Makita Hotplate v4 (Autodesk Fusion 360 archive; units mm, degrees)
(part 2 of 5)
extrude "Extrude34" add of existing geometry to an object second side blind 75
extrude "Extrude35" add of existing geometry blind 5
extrude "Extrude36" cut of existing geometry blind -12 second side blind 30
extrude "Extrude37" add of existing geometry to an object second side blind 0
extrude "Extrude38" cut of existing geometry blind 65
sketch "Sketch30" plane through (0, -5, 0) normal (0, -1, 0) x axis (1, 0, 0)
  line L1 (140.75, 37) -> (140.75, 20)
  line L2 (149.25, 37) -> (140.75, 37)
  line L3 (149.25, 20) -> (149.25, 37)
  line L4 (140.75, 20) -> (149.25, 20)
  line L5 (151.0284, 39) -> (160, 39)
  curve K1 (151.0284, 39) -> (148.2, 41.8284)
  line L6 (148.2, 46) -> (148.2, 41.8284)
  line L7 (142.2, 46) -> (148.2, 46)
  line L8 (142.2, 63) -> (142.2, 46)
  line L9 (148.2, 63) -> (142.2, 63)
  line L10 (148.2, 65.1716) -> (148.2, 63)
  curve K2 (148.2, 65.1716) -> (151.0284, 68)
  line L11 (160, 68) -> (151.0284, 68)
  line L12 (136.3688, 74.3543) -> (162.8374, 74.3543)
  line L13 (136.3688, 86.3543) -> (136.3688, 74.3543)
  line L14 (162.8374, 86.3543) -> (136.3688, 86.3543)
  line L15 (162.8374, 74.3543) -> (162.8374, 86.3543)
  line L16 (162.8374, 9.3543) -> (136.3688, 9.3543)
  line L17 (162.8374, 0) -> (162.8374, 9.3543)
  line L18 (188, 0) -> (162.8374, 0)
  line L19 (188, 120) -> (188, 0)
  line L20 (105.65, 120) -> (188, 120)
  line L21 (105.65, 114) -> (105.65, 120)
  line L22 (109.65, 114) -> (105.65, 114)
  line L23 (109.65, 96.75) -> (109.65, 114)
  line L24 (107, 96.75) -> (109.65, 96.75)
  line L25 (107, 23.25) -> (107, 96.75)
  line L26 (104.5, 23.25) -> (107, 23.25)
  line L27 (104.5, 15.3775) -> (104.5, 23.25)
  line L28 (108.4, 12) -> (104.5, 15.3775)
  line L29 (104.5, 8.6225) -> (108.4, 12)
  line L30 (104.5, 0) -> (104.5, 8.6225)
  line L31 (136.3688, 0) -> (104.5, 0)
  line L32 (136.3688, 9.3543) -> (136.3688, 0)
  line L33 (162.8374, 86.3543) -> (136.3688, 86.3543)
  line L34 (162.8374, 74.3543) -> (162.8374, 86.3543)
  line L35 (136.3688, 74.3543) -> (162.8374, 74.3543)
  line L36 (136.3688, 86.3543) -> (136.3688, 74.3543)
  line L37 (162.8374, 9.3543) -> (136.3688, 9.3543)
  line L38 (162.8374, 0) -> (162.8374, 9.3543)
  line L39 (136.3688, 0) -> (162.8374, 0)
  line L40 (136.3688, 9.3543) -> (136.3688, 0)
  line L41 (134.3688, 11.3543) -> (134.3688, -2)
  line L42 (164.8374, 11.3543) -> (134.3688, 11.3543)
  line L43 (164.8374, -2) -> (164.8374, 11.3543)
  line L44 (134.3688, -2) -> (164.8374, -2)
  line L45 (134.3688, 72.3543) -> (164.8374, 72.3543)
  line L46 (134.3688, 88.3543) -> (134.3688, 72.3543)
  line L47 (164.8374, 88.3543) -> (134.3688, 88.3543)
  line L48 (164.8374, 72.3543) -> (164.8374, 88.3543)
  line L49 (129.3688, 67.3543) -> (169.8374, 67.3543)
  line L50 (129.3688, 93.3543) -> (129.3688, 67.3543)
  line L51 (169.8374, 93.3543) -> (129.3688, 93.3543)
  line L52 (169.8374, 67.3543) -> (169.8374, 93.3543)
  line L53 (129.3688, -7) -> (169.8374, -7)
  line L54 (129.3688, 16.3543) -> (129.3688, -7)
  line L55 (169.8374, 16.3543) -> (129.3688, 16.3543)
  line L56 (169.8374, -7) -> (169.8374, 16.3543)
  line L57 (169.8374, 11.3543) -> (164.8374, 11.3543)
  line L58 (129.3688, 11.3543) -> (134.3688, 11.3543)
  line L59 (129.3688, 88.3543) -> (134.3688, 88.3543)
  line L60 (169.8374, 88.3543) -> (164.8374, 88.3543)
  line L61 (169.8374, 72.3543) -> (164.8374, 72.3543)
  line L62 (129.3688, 72.3543) -> (134.3688, 72.3543)
  arc A1 centre (160, 53.5) radius 14.5 clockwise from (160, 68) to (160, 39)
  circle C1 centre (178.5716, 64.0954) radius 2.5
  circle C2 centre (179.2174, 45.1209) radius 2.5
  circle C3 centre (122, 63.323) radius 2.5
  circle C4 centre (122, 45.196) radius 2.5
  circle C5 centre (122, 91.677) radius 2.5
  circle C6 centre (177.2062, 109.804) radius 2.5
  circle C7 centre (122, 109.804) radius 2.5
  circle C8 centre (177.2062, 91.677) radius 2.5
  circle C9 centre (115, 108) radius 1.65
  circle C10 centre (180.5, 54) radius 1.65
  circle C11 centre (111, 12) radius 1.65
  point P52 (162.8374, 74.3543)
  point P55 (162.8374, 74.3543)
  point P19 (136.3688, 86.3543)
  point P53 (136.3688, 86.3543)
  point P50 (162.8374, 0)
  point P59 (162.8374, 0)
  point P49 (136.3688, 9.3543)
  point P57 (136.3688, 9.3543)
  point P77 (169.8374, 11.3543)
  point P78 (129.3688, 11.3543)
  point P79 (129.3688, 88.3543)
  point P80 (169.8374, 88.3543)
  point P81 (169.8374, 72.3543)
  point P82 (129.3688, 72.3543)
  horizontal L33
  vertical L34
  horizontal L35
  vertical L36
  coincident P52 P55
  coincident P19 P53
  horizontal L37
  vertical L38
  horizontal L39
  vertical L40
  coincident P50 P59
  coincident P49 P57
  coincident L56 P77
  perpendicular L56 L57
  coincident L54 P78
  perpendicular L54 L58
  coincident L50 P79
  perpendicular L50 L59
  coincident L52 P80
  perpendicular L52 L60
  coincident L52 P81
  perpendicular L52 L61
  coincident L50 P82
  perpendicular L50 L62
  dimension "d151" = -2
  dimension "d152" = -2
  dimension "d153" = -7
  dimension "d154" = -7
extrude "Extrude39" cut sketch "Sketch30" profile of L12 L13 L14 L15 L16 L17 L18 L31 L32 L33 L34 L35 L36 L37 L38 L40 L43 L42 L41 L48 L47 L46 L45 L52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 against normal blind 30
sketch "Sketch31" plane through (0, -5, 0) normal (0, -1, 0) x axis (1, 0, 0)
  line L1 (169.8374, 0) -> (169.8374, 11.3543)
  line L2 (188, 0) -> (169.8374, 0)
  line L3 (188, 120) -> (188, 0)
  line L4 (105.65, 120) -> (188, 120)
  line L5 (105.65, 114) -> (105.65, 120)
  line L6 (109.65, 114) -> (105.65, 114)
  line L7 (109.65, 96.75) -> (109.65, 114)
  line L8 (107, 96.75) -> (109.65, 96.75)
  line L9 (107, 23.25) -> (107, 96.75)
  line L10 (104.5, 23.25) -> (107, 23.25)
  line L11 (104.5, 15.3775) -> (104.5, 23.25)
  line L12 (108.4, 12) -> (104.5, 15.3775)
  line L13 (104.5, 8.6225) -> (108.4, 12)
  line L14 (104.5, 0) -> (104.5, 8.6225)
  line L15 (129.3688, 0) -> (104.5, 0)
  line L16 (129.3688, 11.3543) -> (129.3688, 0)
  line L17 (169.8374, 11.3543) -> (129.3688, 11.3543)
  line L18 (169.8374, 72.3543) -> (169.8374, 88.3543)
  line L19 (129.3688, 72.3543) -> (169.8374, 72.3543)
  line L20 (129.3688, 88.3543) -> (129.3688, 72.3543)
  line L21 (169.8374, 88.3543) -> (129.3688, 88.3543)
  line L22 (140.75, 37) -> (140.75, 20)
  line L23 (149.25, 37) -> (140.75, 37)
  line L24 (149.25, 20) -> (149.25, 37)
  line L25 (140.75, 20) -> (149.25, 20)
  line L26 (151.0284, 39) -> (160, 39)
  curve K1 (151.0284, 39) -> (148.2, 41.8284)
  line L27 (148.2, 46) -> (148.2, 41.8284)
  line L28 (142.2, 46) -> (148.2, 46)
  line L29 (142.2, 63) -> (142.2, 46)
  line L30 (148.2, 63) -> (142.2, 63)
  line L31 (148.2, 65.1716) -> (148.2, 63)
  curve K2 (148.2, 65.1716) -> (151.0284, 68)
  line L32 (160, 68) -> (151.0284, 68)
  line L33 (141.3688, 74.3543) -> (136.3688, 74.3543)
  line L34 (141.3688, 86.3543) -> (141.3688, 74.3543)
  line L35 (136.3688, 86.3543) -> (141.3688, 86.3543)
  line L36 (136.3688, 74.3543) -> (136.3688, 86.3543)
  line L37 (150.2964, 74.3543) -> (148.9098, 74.3543)
  line L38 (150.2964, 86.3543) -> (150.2964, 74.3543)
  line L39 (148.9098, 86.3543) -> (150.2964, 86.3543)
  line L40 (148.9098, 74.3543) -> (148.9098, 86.3543)
  line L41 (129.3688, 80.3543) -> (136.3688, 80.3543)
  line L42 (136.3688, 86.3543) -> (136.3688, 80.3543)
  line L43 (129.3688, 83.3543) -> (136.3688, 83.3543)
  line L44 (149.6031, 90.081) -> (149.6031, 86.3543)
  line L45 (162.8374, 74.3543) -> (157.8374, 74.3543)
  line L46 (162.8374, 86.3543) -> (162.8374, 74.3543)
  line L47 (157.8374, 86.3543) -> (162.8374, 86.3543)
  line L48 (157.8374, 74.3543) -> (157.8374, 86.3543)
  line L49 (136.3688, 9.3543) -> (141.3688, 9.3543)
  line L50 (136.3688, 0) -> (136.3688, 9.3543)
  line L51 (141.3688, 0) -> (136.3688, 0)
  line L52 (141.3688, 9.3543) -> (141.3688, 0)
  line L53 (148.9098, 9.3543) -> (150.2964, 9.3543)
  line L54 (148.9098, 0) -> (148.9098, 9.3543)
  line L55 (150.2964, 0) -> (148.9098, 0)
  line L56 (150.2964, 9.3543) -> (150.2964, 0)
  line L57 (157.8374, 9.3543) -> (162.8374, 9.3543)
  line L58 (157.8374, 0) -> (157.8374, 9.3543)
  line L59 (162.8374, 0) -> (157.8374, 0)
  line L60 (162.8374, 9.3543) -> (162.8374, 0)
  line L61 (149.6031, -2.4605) -> (149.6031, 0)
  arc A1 centre (160, 53.5) radius 14.5 clockwise from (160, 68) to (160, 39)
  circle C1 centre (178.5716, 64.0954) radius 2.5
  circle C2 centre (179.2174, 45.1209) radius 2.5
  circle C3 centre (122, 63.323) radius 2.5
  circle C4 centre (122, 45.196) radius 2.5
  circle C5 centre (122, 91.677) radius 2.5
  circle C6 centre (177.2062, 109.804) radius 2.5
  circle C7 centre (122, 109.804) radius 2.5
  circle C8 centre (177.2062, 91.677) radius 2.5
  circle C9 centre (115, 108) radius 1.65
  circle C10 centre (180.5, 54) radius 1.65
  circle C11 centre (111, 12) radius 1.65
  arc A2 centre (131.132, 83.3543) radius 1.7632 clockwise from (129.3688, 83.3543) to (132.8953, 83.3543)
  arc A3 centre (134.632, 83.3543) radius 1.7368 clockwise from (136.3688, 83.3543) to (132.8953, 83.3543)
  arc A4 centre (131.132, 83.3543) radius 0.7632 clockwise from (130.3688, 83.3543) to (131.8953, 83.3543)
  arc A5 centre (134.632, 83.3543) radius 2.7368 clockwise from (137.3688, 83.3543) to (131.8953, 83.3543)
  arc A6 centre (129.3688, 83.3543) radius 1 clockwise from (129.3688, 84.3543) to (129.6524, 84.3132)
  arc A7 centre (129.3688, 83.3543) radius 1 clockwise from (130.3688, 83.3543) to (129.3688, 82.3543)
  arc A8 centre (168.0742, 83.3543) radius 1.7632 clockwise from (166.311, 83.3543) to (169.8374, 83.3543)
  arc A9 centre (169.8374, 83.3543) radius 1 clockwise from (169.8374, 82.3543) to (168.8374, 83.3543)
  arc A10 centre (168.0742, 83.3543) radius 0.7632 clockwise from (167.311, 83.3543) to (168.8374, 83.3543)
  arc A11 centre (164.5742, 83.3543) radius 2.7368 clockwise from (167.311, 83.3543) to (161.8374, 83.3543)
  arc A12 centre (164.5742, 83.3543) radius 1.7368 clockwise from (166.311, 83.3543) to (162.8374, 83.3543)
  arc A13 centre (129.3688, 77.3543) radius 1 clockwise from (129.3688, 78.3543) to (130.3688, 77.3543)
  arc A14 centre (131.132, 77.3543) radius 0.7632 clockwise from (131.8953, 77.3543) to (130.3688, 77.3543)
  arc A15 centre (131.132, 77.3543) radius 1.7632 clockwise from (132.8953, 77.3543) to (129.3688, 77.3543)
  arc A16 centre (134.632, 77.3543) radius 1.7368 clockwise from (132.8953, 77.3543) to (136.3688, 77.3543)
  arc A17 centre (134.632, 77.3543) radius 2.7368 clockwise from (131.8953, 77.3543) to (137.3688, 77.3543)
  arc A18 centre (164.5742, 77.3543) radius 1.7368 clockwise from (162.8374, 77.3543) to (166.311, 77.3543)
  arc A19 centre (164.5742, 77.3543) radius 2.7368 clockwise from (161.8374, 77.3543) to (167.311, 77.3543)
  arc A20 centre (168.0742, 77.3543) radius 1.7632 clockwise from (169.8374, 77.3543) to (166.311, 77.3543)
  arc A21 centre (168.0742, 77.3543) radius 0.7632 clockwise from (168.8374, 77.3543) to (167.311, 77.3543)
  arc A22 centre (169.8374, 77.3543) radius 1 clockwise from (168.8374, 77.3543) to (169.8374, 78.3543)
  arc A23 centre (134.632, 8.3543) radius 1.7368 clockwise from (136.3688, 8.3543) to (132.8953, 8.3543)
  arc A24 centre (131.132, 8.3543) radius 1.7632 clockwise from (129.3688, 8.3543) to (132.8953, 8.3543)
  arc A25 centre (129.3688, 8.3543) radius 1 clockwise from (130.3688, 8.3543) to (129.3688, 7.3543)
  arc A26 centre (131.132, 8.3543) radius 0.7632 clockwise from (130.3688, 8.3543) to (131.8953, 8.3543)
  arc A27 centre (134.632, 8.3543) radius 2.7368 clockwise from (137.3688, 8.3543) to (131.8953, 8.3543)
  arc A28 centre (134.632, 2.3543) radius 1.7368 clockwise from (132.8953, 2.3543) to (136.3688, 2.3543)
  arc A29 centre (134.632, 2.3543) radius 2.7368 clockwise from (131.8953, 2.3543) to (137.3688, 2.3543)
  arc A30 centre (131.132, 2.3543) radius 1.7632 clockwise from (132.8953, 2.3543) to (129.3688, 2.3543)
  arc A31 centre (131.132, 2.3543) radius 0.7632 clockwise from (131.8953, 2.3543) to (130.3688, 2.3543)
  arc A32 centre (129.3688, 2.3543) radius 1 clockwise from (129.3688, 3.3543) to (130.3688, 2.3543)
  arc A33 centre (169.8374, 2.3543) radius 1 clockwise from (168.8374, 2.3543) to (169.8374, 3.3543)
  arc A34 centre (169.8374, 8.3543) radius 1 clockwise from (169.8374, 7.3543) to (168.8374, 8.3543)
  arc A35 centre (164.5742, 2.3543) radius 2.7368 clockwise from (161.8374, 2.3543) to (167.311, 2.3543)
  arc A36 centre (168.0742, 8.3543) radius 0.7632 clockwise from (167.311, 8.3543) to (168.8374, 8.3543)
  arc A37 centre (168.0742, 8.3543) radius 1.7632 clockwise from (166.311, 8.3543) to (169.8374, 8.3543)
  arc A38 centre (164.5742, 8.3543) radius 1.7368 clockwise from (166.311, 8.3543) to (162.8374, 8.3543)
  arc A39 centre (168.0742, 2.3543) radius 0.7632 clockwise from (168.8374, 2.3543) to (167.311, 2.3543)
  arc A40 centre (168.0742, 2.3543) radius 1.7632 clockwise from (169.8374, 2.3543) to (166.311, 2.3543)
  arc A41 centre (164.5742, 8.3543) radius 2.7368 clockwise from (167.311, 8.3543) to (161.8374, 8.3543)
  arc A42 centre (164.5742, 2.3543) radius 1.7368 clockwise from (162.8374, 2.3543) to (166.311, 2.3543)
  point P57 (136.3688, 80.3543)
  point P58 (129.3688, 80.3543)
  point P52 (136.3688, 86.3543)
  point P59 (136.3688, 86.3543)
  point P60 (136.3688, 83.3543)
  point P61 (129.3688, 83.3543)
  point P62 (131.132, 83.3543)
  point P63 (134.632, 83.3543)
  point P64 (132.8953, 83.3543)
  point P70 (129.3688, 83.3543)
  point P71 (149.6031, 86.3543)
  point P73 (129.6524, 84.3132)
  point P74 (129.3688, 84.3543)
  point P75 (129.3688, 82.3543)
  point P88 (162.8374, 83.3543)
  point P79 (169.8374, 83.3543)
  point P78 (166.311, 83.3543)
  point P66 (131.8953, 83.3543)
  point P84 (167.311, 83.3543)
  point P67 (130.3688, 83.3543)
  point P82 (168.8374, 83.3543)
  point P69 (137.3688, 83.3543)
  point P86 (161.8374, 83.3543)
  point P81 (169.8374, 82.3543)
  point P102 (136.3688, 77.3543)
  point P100 (129.3688, 77.3543)
  point P99 (132.8953, 77.3543)
  point P97 (131.8953, 77.3543)
  point P95 (130.3688, 77.3543)
  point P104 (137.3688, 77.3543)
  point P94 (129.3688, 78.3543)
  point P107 (166.311, 77.3543)
  point P112 (169.8374, 77.3543)
  point P116 (169.8374, 78.3543)
  point P114 (168.8374, 77.3543)
  point P110 (167.311, 77.3543)
  point P109 (161.8374, 77.3543)
  point P106 (162.8374, 77.3543)
  point P153 (149.6031, 0)
  point P117 (132.8953, 8.3543)
  point P157 (166.311, 8.3543)
  point P118 (136.3688, 8.3543)
  point P173 (162.8374, 8.3543)
  point P120 (131.8953, 8.3543)
  point P158 (167.311, 8.3543)
  point P121 (130.3688, 8.3543)
  point P162 (168.8374, 8.3543)
  point P123 (137.3688, 8.3543)
  point P176 (161.8374, 8.3543)
  point P125 (132.8953, 2.3543)
  point P161 (166.311, 2.3543)
  point P126 (129.3688, 3.3543)
  point P166 (169.8374, 3.3543)
  point P127 (130.3688, 2.3543)
  point P156 (168.8374, 2.3543)
  point P129 (131.8953, 2.3543)
  point P155 (167.311, 2.3543)
  point P131 (129.3688, 2.3543)
  point P174 (169.8374, 2.3543)
  point P133 (136.3688, 2.3543)
  point P178 (162.8374, 2.3543)
  point P135 (137.3688, 2.3543)
  point P170 (161.8374, 2.3543)
  point P136 (129.3688, 7.3543)
  point P168 (169.8374, 7.3543)
  point P140 (129.3688, 8.3543)
  point P171 (169.8374, 8.3543)
  midpoint L36 P57
  midpoint L20 P58
  coincident P52 P59
  midpoint L42 P60
  coincident L20 P61
  perpendicular L20 L43
  coincident L43 P62
  coincident L43 P63
  tangent A2 A3
  tangent L42 A3
  coincident L43 P64
  coincident P61 P70
  tangent A4 A6
  midpoint L39 P71
  perpendicular L39 L44
  coincident A2 P73
  coincident L20 P74
  coincident L20 P75
  concentric A6 A7
  symmetric P60 L44 P88
  symmetric P61 L44 P79
  symmetric P64 L44 P78
  symmetric A2 L44 A8
  symmetric A3 L44 A12
  symmetric P66 L44 P84
  symmetric P67 L44 P82
  symmetric A4 L44 A10
  symmetric P69 L44 P86
  symmetric A5 L44 A11
  symmetric L44 P75 P81
  symmetric L44 A7 A9
  symmetric L41 P60 P102
  symmetric L41 P61 P100
  symmetric L41 P64 P99
  symmetric L41 A2 A15
  symmetric L41 A3 A16
  symmetric L41 P66 P97
  symmetric L41 P67 P95
  symmetric L41 A4 A14
  symmetric L41 P69 P104
  symmetric L41 A5 A17
  symmetric L41 P75 P94
  symmetric L41 A7 A13
  symmetric L41 P78 P107
  symmetric L41 P79 P112
  symmetric L41 A8 A20
  symmetric L41 P81 P116
  symmetric L41 P82 P114
  symmetric L41 A9 A22
  symmetric L41 P84 P110
  symmetric L41 A10 A21
  symmetric L41 P86 P109
  symmetric L41 A11 A19
  symmetric L41 P88 P106
  symmetric L41 A12 A18
  tangent A23 A24
  midpoint L55 P153
  perpendicular L55 L61
  symmetric P117 L61 P157
  symmetric P118 L61 P173
  symmetric P120 L61 P158
  symmetric P121 L61 P162
  symmetric P123 L61 P176
  symmetric P125 L61 P161
  symmetric P126 L61 P166
  symmetric P127 L61 P156
  symmetric P129 L61 P155
  symmetric P131 L61 P174
  symmetric P133 L61 P178
  symmetric P135 L61 P170
  symmetric P136 L61 P168
  symmetric P140 L61 P171
  symmetric A23 L61 A38
  symmetric A24 L61 A37
  symmetric A25 L61 A34
  symmetric A26 L61 A36
  symmetric A27 L61 A41
  symmetric A28 L61 A42
  symmetric A29 L61 A35
  symmetric A30 L61 A40
  symmetric A31 L61 A39
  symmetric A32 L61 A33
  dimension "d157" = 1
  dimension "d162" = 1
extrude "Extrude40" add sketch "Sketch31" profile of L18 L20 L36 L42 A2 A3 A5 A4 A7 A8 A9 A10 A11 A12 L46 A13 A14 A15 A16 A17 A18 A19 A20 A21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 to an object
fillet "Fillet5" radius 3.5 bodies "Body1 (1)"
extrude "Extrude41" add sketch "Sketch31" profile of L1 L16 A23 A24 A25 A28 A29 A30 A31 A32 A26 A27 L50 L60 A33 A34 A35 A36 A37 A38 A39 A40 A41 A42 to an object
fillet "Fillet6" radius 1 bodies "Body1 (1)"
fillet "Fillet7" radius 1 bodies "Body1 (1)"
extrude "Extrude42" cut of existing geometry blind -1
extrude "Extrude43" cut of existing geometry blind -1
fillet "Fillet8" radius 1 bodies "Body1 (1)"
sketch "Sketch32" plane through (0, 5, 0) normal (0, 1, 0) x axis (-1, 0, 0)
  line L1 (-137.3688, 75.3543) -> (-161.8374, 75.3543)
  line L2 (-136.3688, 77.3543) -> (-136.3688, 76.3543)
  line L3 (-129.3688, 75.8543) -> (-129.3688, 77.3543)
  line L4 (-166.3374, 72.3543) -> (-132.8688, 72.3543)
  line L5 (-169.8374, 77.3543) -> (-169.8374, 75.8543)
  line L6 (-162.8374, 76.3543) -> (-162.8374, 77.3543)
  line L7 (-129.3688, 78.3543) -> (-129.3688, 82.3543)
  line L8 (-136.3688, 81.2392) -> (-136.3688, 79.4694)
  line L9 (-149.25, 37) -> (-149.25, 20)
  line L10 (-140.75, 37) -> (-149.25, 37)
  line L11 (-140.75, 20) -> (-140.75, 37)
  line L12 (-149.25, 20) -> (-140.75, 20)
  line L13 (-148.2, 63) -> (-148.2, 65.1716)
  line L14 (-145.5, 63) -> (-148.2, 63)
  line L15 (-145.5, 46) -> (-145.5, 63)
  line L16 (-148.2, 46) -> (-145.5, 46)
  line L17 (-148.2, 41.8284) -> (-148.2, 46)
  curve K1 (-148.2, 41.8284) -> (-151.0284, 39)
  line L18 (-160, 39) -> (-151.0284, 39)
  line L19 (-151.0284, 68) -> (-160, 68)
  curve K2 (-151.0284, 68) -> (-148.2, 65.1716)
  line L20 (-169.8374, 82.3543) -> (-169.8374, 78.3543)
  line L21 (-162.8374, 79.4694) -> (-162.8374, 81.2392)
  line L22 (-136.3688, 6.2392) -> (-136.3688, 4.4694)
  line L23 (-129.3688, 3.3543) -> (-129.3688, 7.3543)
  line L24 (-169.8374, 7.3543) -> (-169.8374, 3.3543)
  line L25 (-162.8374, 4.4694) -> (-162.8374, 6.2392)
  line L26 (-169.8374, 2.3543) -> (-169.8374, 1)
  line L27 (-162.8374, 1) -> (-162.8374, 2.3543)
  line L28 (-137.3688, 0) -> (-161.8374, 0)
  line L29 (-136.3688, 2.3543) -> (-136.3688, 1)
  line L30 (-129.3688, 1) -> (-129.3688, 2.3543)
  line L31 (-103.4, 0) -> (-128.3688, 0)
  line L32 (-103.4, 22.25) -> (-103.4, 0)
  line L33 (-103.9, 22.75) -> (-103.4, 22.25)
  line L34 (-107, 22.75) -> (-103.9, 22.75)
  line L35 (-107, 96.75) -> (-107, 22.75)
  line L36 (-113, 96.75) -> (-107, 96.75)
  line L37 (-113, 97.25) -> (-113, 96.75)
  line L38 (-106.2071, 97.25) -> (-113, 97.25)
  line L39 (-105, 98.4571) -> (-106.2071, 97.25)
  line L40 (-105, 114) -> (-105, 98.4571)
  line L41 (-102.65, 114) -> (-105, 114)
  line L42 (-102.65, 120) -> (-102.65, 114)
  line L43 (-188, 120) -> (-102.65, 120)
  line L44 (-188, 0) -> (-188, 120)
  line L45 (-170.8374, 0) -> (-188, 0)
  line L46 (-169.8374, 10.3543) -> (-169.8374, 8.3543)
  line L47 (-130.3688, 11.3543) -> (-168.8374, 11.3543)
  line L48 (-129.3688, 8.3543) -> (-129.3688, 10.3543)
  line L49 (-161.8374, 9.3543) -> (-137.3688, 9.3543)
  line L50 (-161.8374, 85.3543) -> (-137.3688, 85.3543)
  line L51 (-162.8374, 83.3543) -> (-162.8374, 84.3543)
  line L52 (-169.8374, 84.8543) -> (-169.8374, 83.3543)
  line L53 (-132.8688, 88.3543) -> (-166.3374, 88.3543)
  line L54 (-129.3688, 83.3543) -> (-129.3688, 84.8543)
  line L55 (-136.3688, 84.3543) -> (-136.3688, 83.3543)
  arc A1 centre (-161.8374, 76.3543) radius 1 clockwise from (-161.8374, 75.3543) to (-162.8374, 76.3543)
  arc A2 centre (-137.3688, 76.3543) radius 1 clockwise from (-136.3688, 76.3543) to (-137.3688, 75.3543)
  arc A3 centre (-134.632, 77.3543) radius 1.7368 clockwise from (-136.3688, 77.3543) to (-132.8953, 77.3543)
  arc A4 centre (-131.132, 77.3543) radius 1.7632 clockwise from (-129.3688, 77.3543) to (-132.8953, 77.3543)
  arc A5 centre (-132.8688, 75.8543) radius 3.5 clockwise from (-129.3688, 75.8543) to (-132.8688, 72.3543)
  arc A6 centre (-166.3374, 75.8543) radius 3.5 clockwise from (-166.3374, 72.3543) to (-169.8374, 75.8543)
  arc A7 centre (-168.0742, 77.3543) radius 1.7632 clockwise from (-166.311, 77.3543) to (-169.8374, 77.3543)
  arc A8 centre (-164.5742, 77.3543) radius 1.7368 clockwise from (-166.311, 77.3543) to (-162.8374, 77.3543)
  arc A9 centre (-134.632, 83.3543) radius 2.7368 clockwise from (-131.8953, 83.3543) to (-136.3688, 81.2392)
  arc A10 centre (-131.132, 83.3543) radius 0.7632 clockwise from (-131.8953, 83.3543) to (-130.3688, 83.3543)
  arc A11 centre (-129.3688, 83.3543) radius 1 clockwise from (-129.3688, 82.3543) to (-130.3688, 83.3543)
  arc A12 centre (-129.3688, 77.3543) radius 1 clockwise from (-130.3688, 77.3543) to (-129.3688, 78.3543)
  arc A13 centre (-131.132, 77.3543) radius 0.7632 clockwise from (-130.3688, 77.3543) to (-131.8953, 77.3543)
  arc A14 centre (-134.632, 77.3543) radius 2.7368 clockwise from (-136.3688, 79.4694) to (-131.8953, 77.3543)
  circle C1 centre (-178.5716, 64.0954) radius 4.85
  circle C2 centre (-122, 63.323) radius 4.85
  circle C3 centre (-122, 109.804) radius 4.85
  circle C4 centre (-177.2062, 109.804) radius 4.85
  circle C5 centre (-111, 12) radius 1.65
  circle C6 centre (-115, 108) radius 1.65
  circle C7 centre (-180.5, 54) radius 1.65
  arc A15 centre (-160, 53.5) radius 14.5 clockwise from (-160, 39) to (-160, 68)
  circle C8 centre (-177.2062, 91.677) radius 4.85
  circle C9 centre (-122, 91.677) radius 4.85
  circle C10 centre (-122, 45.196) radius 4.85
  circle C11 centre (-179.2174, 45.1209) radius 4.85
  arc A16 centre (-164.5742, 77.3543) radius 2.7368 clockwise from (-167.311, 77.3543) to (-162.8374, 79.4694)
  arc A17 centre (-168.0742, 77.3543) radius 0.7632 clockwise from (-167.311, 77.3543) to (-168.8374, 77.3543)
  arc A18 centre (-169.8374, 77.3543) radius 1 clockwise from (-169.8374, 78.3543) to (-168.8374, 77.3543)
  arc A19 centre (-169.8374, 83.3543) radius 1 clockwise from (-168.8374, 83.3543) to (-169.8374, 82.3543)
  arc A20 centre (-168.0742, 83.3543) radius 0.7632 clockwise from (-168.8374, 83.3543) to (-167.311, 83.3543)
  arc A21 centre (-164.5742, 83.3543) radius 2.7368 clockwise from (-162.8374, 81.2392) to (-167.311, 83.3543)
  arc A22 centre (-134.632, 8.3543) radius 2.7368 clockwise from (-131.8953, 8.3543) to (-136.3688, 6.2392)
  arc A23 centre (-131.132, 8.3543) radius 0.7632 clockwise from (-131.8953, 8.3543) to (-130.3688, 8.3543)
  arc A24 centre (-129.3688, 8.3543) radius 1 clockwise from (-129.3688, 7.3543) to (-130.3688, 8.3543)
  arc A25 centre (-129.3688, 2.3543) radius 1 clockwise from (-130.3688, 2.3543) to (-129.3688, 3.3543)
  arc A26 centre (-131.132, 2.3543) radius 0.7632 clockwise from (-130.3688, 2.3543) to (-131.8953, 2.3543)
  arc A27 centre (-134.632, 2.3543) radius 2.7368 clockwise from (-136.3688, 4.4694) to (-131.8953, 2.3543)
  arc A28 centre (-169.8374, 8.3543) radius 1 clockwise from (-168.8374, 8.3543) to (-169.8374, 7.3543)
  arc A29 centre (-168.0742, 8.3543) radius 0.7632 clockwise from (-168.8374, 8.3543) to (-167.311, 8.3543)
  arc A30 centre (-164.5742, 8.3543) radius 2.7368 clockwise from (-162.8374, 6.2392) to (-167.311, 8.3543)
  arc A31 centre (-164.5742, 2.3543) radius 2.7368 clockwise from (-167.311, 2.3543) to (-162.8374, 4.4694)
  arc A32 centre (-168.0742, 2.3543) radius 0.7632 clockwise from (-167.311, 2.3543) to (-168.8374, 2.3543)
  arc A33 centre (-169.8374, 2.3543) radius 1 clockwise from (-169.8374, 3.3543) to (-168.8374, 2.3543)
  arc A34 centre (-170.8374, 1) radius 1 clockwise from (-169.8374, 1) to (-170.8374, 0)
  arc A35 centre (-168.0742, 2.3543) radius 1.7632 clockwise from (-166.311, 2.3543) to (-169.8374, 2.3543)
  arc A36 centre (-164.5742, 2.3543) radius 1.7368 clockwise from (-166.311, 2.3543) to (-162.8374, 2.3543)
  arc A37 centre (-161.8374, 1) radius 1 clockwise from (-161.8374, 0) to (-162.8374, 1)
  arc A38 centre (-137.3688, 1) radius 1 clockwise from (-136.3688, 1) to (-137.3688, 0)
  arc A39 centre (-134.632, 2.3543) radius 1.7368 clockwise from (-136.3688, 2.3543) to (-132.8953, 2.3543)
  arc A40 centre (-131.132, 2.3543) radius 1.7632 clockwise from (-129.3688, 2.3543) to (-132.8953, 2.3543)
  arc A41 centre (-128.3688, 1) radius 1 clockwise from (-128.3688, 0) to (-129.3688, 1)
  arc A42 centre (-161.8374, 8.3543) radius 1 clockwise from (-162.8374, 8.3543) to (-161.8374, 9.3543)
  arc A43 centre (-164.5742, 8.3543) radius 1.7368 clockwise from (-162.8374, 8.3543) to (-166.311, 8.3543)
  arc A44 centre (-168.0742, 8.3543) radius 1.7632 clockwise from (-169.8374, 8.3543) to (-166.311, 8.3543)
  arc A45 centre (-168.8374, 10.3543) radius 1 clockwise from (-169.8374, 10.3543) to (-168.8374, 11.3543)
  arc A46 centre (-130.3688, 10.3543) radius 1 clockwise from (-130.3688, 11.3543) to (-129.3688, 10.3543)
  arc A47 centre (-131.132, 8.3543) radius 1.7632 clockwise from (-132.8953, 8.3543) to (-129.3688, 8.3543)
  arc A48 centre (-134.632, 8.3543) radius 1.7368 clockwise from (-132.8953, 8.3543) to (-136.3688, 8.3543)
  arc A49 centre (-137.3688, 8.3543) radius 1 clockwise from (-137.3688, 9.3543) to (-136.3688, 8.3543)
  arc A50 centre (-137.3688, 84.3543) radius 1 clockwise from (-137.3688, 85.3543) to (-136.3688, 84.3543)
  arc A51 centre (-161.8374, 84.3543) radius 1 clockwise from (-162.8374, 84.3543) to (-161.8374, 85.3543)
  arc A52 centre (-164.5742, 83.3543) radius 1.7368 clockwise from (-162.8374, 83.3543) to (-166.311, 83.3543)
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sketch "Sketch33" plane through (145.325, 5, 60) normal (0, 1, 0) x axis (-1, 0, 0)
  line L1 (-17.5124, 19.4694) -> (-17.5124, 21.2392)
  line L2 (-16.5124, 25.3543) -> (7.9562, 25.3543)
  line L3 (-4.2781, 23.4223) -> (-4.2781, 25.3543)
  line L4 (-14.8628, 20.3543) -> (-17.5124, 20.3543)
  line L5 (-13.5124, 16.8902) -> (-16.5124, 18.6222)
  line L6 (-10.5124, 18.6222) -> (-13.5124, 16.8902)
  line L7 (-10.5124, 22.0863) -> (-10.5124, 18.6222)
  line L8 (-13.5124, 23.8184) -> (-10.5124, 22.0863)
  line L9 (-16.5124, 22.0863) -> (-13.5124, 23.8184)
  line L10 (-16.5124, 18.6222) -> (-16.5124, 22.0863)
  line L11 (4.9562, 16.8902) -> (7.9562, 18.6222)
  line L12 (7.9562, 18.6222) -> (7.9562, 22.0863)
  line L13 (7.9562, 22.0863) -> (4.9562, 23.8184)
  line L14 (4.9562, 23.8184) -> (1.9562, 22.0863)
  line L15 (1.9562, 22.0863) -> (1.9562, 18.6222)
  line L16 (1.9562, 18.6222) -> (4.9562, 16.8902)
  line L17 (7.9562, 15.3543) -> (-16.5124, 15.3543)
  line L18 (8.9562, 17.3543) -> (8.9562, 16.3543)
  line L19 (15.9562, 15.8543) -> (15.9562, 17.3543)
  line L20 (-21.0124, 12.3543) -> (12.4562, 12.3543)
  line L21 (-24.5124, 17.3543) -> (-24.5124, 15.8543)
  line L22 (-17.5124, 16.3543) -> (-17.5124, 17.3543)
  line L23 (15.9562, 18.3543) -> (15.9562, 22.3543)
  line L24 (8.9562, 21.2392) -> (8.9562, 19.4694)
  line L25 (-3.925, -23) -> (-3.925, -40)
  line L26 (4.575, -23) -> (-3.925, -23)
  line L27 (4.575, -40) -> (4.575, -23)
  line L28 (-3.925, -40) -> (4.575, -40)
  line L29 (-2.875, 3) -> (-2.875, 5.1716)
  line L30 (-0.175, 3) -> (-2.875, 3)
  line L31 (-0.175, -14) -> (-0.175, 3)
  line L32 (-2.875, -14) -> (-0.175, -14)
  line L33 (-2.875, -18.1716) -> (-2.875, -14)
  curve K1 (-2.875, -18.1716) -> (-5.7034, -21)
  line L34 (-14.675, -21) -> (-5.7034, -21)
  line L35 (-5.7034, 8) -> (-14.675, 8)
  curve K2 (-5.7034, 8) -> (-2.875, 5.1716)
  line L36 (-24.5124, 22.3543) -> (-24.5124, 18.3543)
  line L37 (-17.5124, 19.4694) -> (-17.5124, 21.2392)
  line L38 (8.9562, -53.7608) -> (8.9562, -55.5306)
  line L39 (15.9562, -56.6457) -> (15.9562, -52.6457)
  line L40 (-24.5124, -52.6457) -> (-24.5124, -56.6457)
  line L41 (-17.5124, -55.5306) -> (-17.5124, -53.7608)
  line L42 (-24.5124, -57.6457) -> (-24.5124, -59)
  line L43 (-17.5124, -59) -> (-17.5124, -57.6457)
  line L44 (7.9562, -60) -> (-16.5124, -60)
  line L45 (8.9562, -57.6457) -> (8.9562, -59)
  line L46 (15.9562, -59) -> (15.9562, -57.6457)
  line L47 (41.925, -60) -> (16.9562, -60)
  line L48 (41.925, -37.75) -> (41.925, -60)
  line L49 (41.425, -37.25) -> (41.925, -37.75)
  line L50 (38.325, -37.25) -> (41.425, -37.25)
  line L51 (38.325, 36.75) -> (38.325, -37.25)
  line L52 (32.325, 36.75) -> (38.325, 36.75)
  line L53 (32.325, 37.25) -> (32.325, 36.75)
  line L54 (39.1179, 37.25) -> (32.325, 37.25)
  line L55 (40.325, 38.4571) -> (39.1179, 37.25)
  line L56 (40.325, 54) -> (40.325, 38.4571)
  line L57 (42.675, 54) -> (40.325, 54)
  line L58 (42.675, 60) -> (42.675, 54)
  line L59 (-42.675, 60) -> (42.675, 60)
  line L60 (-42.675, -60) -> (-42.675, 60)
  line L61 (-25.5124, -60) -> (-42.675, -60)
  line L62 (-24.5124, -49.6457) -> (-24.5124, -51.6457)
  line L63 (14.9562, -48.6457) -> (-23.5124, -48.6457)
  line L64 (15.9562, -51.6457) -> (15.9562, -49.6457)
  line L65 (-16.5124, -50.6457) -> (7.9562, -50.6457)
  line L66 (-16.5124, 25.3543) -> (7.9562, 25.3543)
  line L67 (-17.5124, 23.3543) -> (-17.5124, 24.3543)
  line L68 (-24.5124, 24.8543) -> (-24.5124, 23.3543)
  line L69 (12.4562, 28.3543) -> (-21.0124, 28.3543)
  line L70 (15.9562, 23.3543) -> (15.9562, 24.8543)
  line L71 (8.9562, 24.3543) -> (8.9562, 23.3543)
  line L72 (-16.5124, -60) -> (-16.5124, -50.6457)
  line L73 (-14.2464, -55.3229) -> (-16.5124, -55.3229)
  line L74 (-13.5124, -58.787) -> (-16.5124, -57.0549)
  line L75 (-10.5124, -57.0549) -> (-13.5124, -58.787)
  line L76 (-10.5124, -53.5908) -> (-10.5124, -57.0549)
  line L77 (-13.5124, -51.8588) -> (-10.5124, -53.5908)
  line L78 (-16.5124, -53.5908) -> (-13.5124, -51.8588)
  line L79 (-16.5124, -57.0549) -> (-16.5124, -53.5908)
  line L80 (-17.5124, -55.5306) -> (-17.5124, -53.7608)
  line L81 (-4.2781, -58.556) -> (-4.2781, -60)
  line L82 (7.9562, -57.0549) -> (7.9562, -53.5908)
  line L83 (7.9562, -53.5908) -> (4.9562, -51.8588)
  line L84 (4.9562, -51.8588) -> (1.9562, -53.5908)
  line L85 (1.9562, -53.5908) -> (1.9562, -57.0549)
  line L86 (1.9562, -57.0549) -> (4.9562, -58.787)
  line L87 (4.9562, -58.787) -> (7.9562, -57.0549)
  circle C1 centre (-13.5124, 20.3543) radius 1.5
  circle C2 centre (4.9562, 20.3543) radius 1.5
  arc A1 centre (-16.5124, 16.3543) radius 1 clockwise from (-16.5124, 15.3543) to (-17.5124, 16.3543)
  arc A2 centre (7.9562, 16.3543) radius 1 clockwise from (8.9562, 16.3543) to (7.9562, 15.3543)
  arc A3 centre (10.693, 17.3543) radius 1.7368 clockwise from (8.9562, 17.3543) to (12.4297, 17.3543)
  arc A4 centre (14.193, 17.3543) radius 1.7632 clockwise from (15.9562, 17.3543) to (12.4297, 17.3543)
  arc A5 centre (12.4562, 15.8543) radius 3.5 clockwise from (15.9562, 15.8543) to (12.4562, 12.3543)
  arc A6 centre (-21.0124, 15.8543) radius 3.5 clockwise from (-21.0124, 12.3543) to (-24.5124, 15.8543)
  arc A7 centre (-22.7492, 17.3543) radius 1.7632 clockwise from (-20.986, 17.3543) to (-24.5124, 17.3543)
  arc A8 centre (-19.2492, 17.3543) radius 1.7368 clockwise from (-20.986, 17.3543) to (-17.5124, 17.3543)
  arc A9 centre (10.693, 23.3543) radius 2.7368 clockwise from (13.4297, 23.3543) to (8.9562, 21.2392)
  arc A10 centre (14.193, 23.3543) radius 0.7632 clockwise from (13.4297, 23.3543) to (14.9562, 23.3543)
  arc A11 centre (15.9562, 23.3543) radius 1 clockwise from (15.9562, 22.3543) to (14.9562, 23.3543)
  arc A12 centre (15.9562, 17.3543) radius 1 clockwise from (14.9562, 17.3543) to (15.9562, 18.3543)
  arc A13 centre (14.193, 17.3543) radius 0.7632 clockwise from (14.9562, 17.3543) to (13.4297, 17.3543)
  arc A14 centre (10.693, 17.3543) radius 2.7368 clockwise from (8.9562, 19.4694) to (13.4297, 17.3543)
  circle C3 centre (-33.2466, 4.0954) radius 4.85
  circle C4 centre (23.325, 3.323) radius 4.85
  circle C5 centre (23.325, 49.804) radius 4.85
  circle C6 centre (-31.8812, 49.804) radius 4.85
  circle C7 centre (34.325, -48) radius 1.65
  circle C8 centre (30.325, 48) radius 1.65
  circle C9 centre (-35.175, -6) radius 1.65
  arc A15 centre (-14.675, -6.5) radius 14.5 clockwise from (-14.675, -21) to (-14.675, 8)
  circle C10 centre (-31.8812, 31.677) radius 4.85
  circle C11 centre (23.325, 31.677) radius 4.85
  circle C12 centre (23.325, -14.804) radius 4.85
  circle C13 centre (-33.8924, -14.8791) radius 4.85
  arc A16 centre (-19.2492, 17.3543) radius 2.7368 clockwise from (-21.986, 17.3543) to (-17.5124, 19.4694)
  arc A17 centre (-22.7492, 17.3543) radius 0.7632 clockwise from (-21.986, 17.3543) to (-23.5124, 17.3543)
  arc A18 centre (-24.5124, 17.3543) radius 1 clockwise from (-24.5124, 18.3543) to (-23.5124, 17.3543)
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  point P6 (-4.2781, 25.3543)
  point P8 (-17.5124, 20.3543)
  point P16 (-13.5124, 20.3543)
  point P17 (-13.5124, 20.3543)
  point P10 (-16.5124, 18.6222)
  point P19 (7.9562, 18.6222)
  point P11 (-13.5124, 16.8902)
  point P20 (4.9562, 16.8902)
  point P12 (-10.5124, 18.6222)
  point P18 (1.9562, 18.6222)
  point P13 (-10.5124, 22.0863)
  point P23 (1.9562, 22.0863)
  point P14 (-13.5124, 23.8184)
  point P22 (4.9562, 23.8184)
  point P15 (-16.5124, 22.0863)
  point P21 (7.9562, 22.0863)
  point P153 (-16.5124, -50.6457)
  point P183 (-16.5124, -50.6457)
  point P129 (-16.5124, -60)
  point P184 (-16.5124, -60)
  point P185 (-16.5124, -55.3229)
  point P193 (-13.5124, -55.3229)
  point P196 (-13.5124, -55.3229)
  point P197 (-4.2781, -60)
  point P187 (-16.5124, -57.0549)
  point P201 (7.9562, -57.0549)
  point P188 (-13.5124, -58.787)
  point P205 (4.9562, -58.787)
  point P189 (-10.5124, -57.0549)
  point P204 (1.9562, -57.0549)
  point P190 (-10.5124, -53.5908)
  point P203 (1.9562, -53.5908)
  point P191 (-13.5124, -51.8588)
  point P202 (4.9562, -51.8588)
  point P192 (-16.5124, -53.5908)
  point P200 (7.9562, -53.5908)
  midpoint L2 P6
  perpendicular L2 L3
  midpoint L1 P8
  perpendicular L1 L4
  coincident L4 P16
  coincident P16 P17
  symmetric L3 P10 P19
  symmetric L3 P11 P20
  symmetric L3 P12 P18
  symmetric L3 P13 P23
  symmetric L3 P14 P22
  symmetric L3 P15 P21
  symmetric L3 C1 C2
  coincident P153 P183
  coincident P129 P184
  midpoint L72 P185
  perpendicular L72 L73
  vertical L10
  vertical L79
  coincident P193 P196
  midpoint L44 P197
  perpendicular L44 L81
  symmetric P187 L81 P201
  symmetric P188 L81 P205
  symmetric P189 L81 P204
  symmetric P190 L81 P203
  symmetric P191 L81 P202
  symmetric P192 L81 P200
  dimension "d175" distance P16 L10 = 3
  dimension "d176" diameter C1 = 3
  dimension "d177" distance P193 L79 = 3
  dimension "d179" distance L1 L10 = 1
  dimension "d180" distance L79 L80 = 1
  dimension "d181" diameter = 3
extrude "Extrude44" cut sketch "Sketch33" against normal blind 4.2
extrude "Extrude45" cut sketch "Sketch33" against normal blind 23.5
sketch "Sketch34" plane through (0, 0, 85.3543) normal (0, 0, 1) x axis (-1, 0, 0)
  line L1 (-137.3688, 12.2242) -> (-137.3688, -5)
  line L2 (-141.3688, 12.2242) -> (-137.3688, 12.2242)
  line L3 (-148.9098, 6.122) -> (-141.3688, 12.2242)
  line L4 (-150.2964, 6.122) -> (-148.9098, 6.122)
  line L5 (-157.8374, 12.2242) -> (-150.2964, 6.122)
  line L6 (-161.8374, 12.2242) -> (-157.8374, 12.2242)
  line L7 (-161.8374, -5) -> (-161.8374, 12.2242)
  line L8 (-137.3688, -5) -> (-161.8374, -5)
  line L9 (-149.6031, 15.6415) -> (-149.6031, 6.122)
  line L10 (-141.4691, 13.8322) -> (-137.4646, 13.8322)
  line L11 (-149.6031, 18.7147) -> (-141.4691, 13.8322)
  line L12 (-157.7371, 13.8322) -> (-161.7416, 13.8322)
  line L13 (-149.6031, 18.7147) -> (-157.7371, 13.8322)
  line L14 (-140.4667, 17.45) -> (-137.4646, 17.45)
  line L15 (-146.0005, 20.7717) -> (-140.4667, 17.45)
  line L16 (-153.2057, 20.7717) -> (-158.7396, 17.45)
  line L17 (-158.7396, 17.45) -> (-161.7416, 17.45)
  line L18 (-136.4646, 17.45) -> (-137.4646, 17.45)
  line L19 (-136.4646, 13.8322) -> (-136.4646, 17.45)
  line L20 (-137.4646, 13.8322) -> (-136.4646, 13.8322)
  line L21 (-137.4646, 17.45) -> (-137.4646, 13.8322)
  line L22 (-162.7416, 17.45) -> (-161.7416, 17.45)
  line L23 (-162.7416, 13.8322) -> (-162.7416, 17.45)
  line L24 (-161.7416, 13.8322) -> (-162.7416, 13.8322)
  line L25 (-161.7416, 17.45) -> (-161.7416, 13.8322)
  circle C1 centre (-149.6031, 12.4598) radius 5.3629
  arc A1 centre (-149.6031, 14.77) radius 7 clockwise from (-153.2057, 20.7717) to (-146.0005, 20.7717)
  point P10 (-149.6031, 6.122)
  point P12 (-149.6031, 12.4598)
  point P13 (-137.4646, 13.8322)
  point P16 (-161.7416, 13.8322)
  point P14 (-141.4691, 13.8322)
  point P15 (-157.7371, 13.8322)
  point P27 (-137.4646, 13.8322)
  point P26 (-136.4646, 13.8322)
  point P21 (-161.7416, 17.45)
  point P28 (-162.7416, 17.45)
  midpoint L4 P10
  perpendicular L4 L9
  coincident L9 P12
  tangent L3 C1
  parallel L2 L10
  tangent C1 L11
  symmetric L9 P13 P16
  symmetric L9 P14 P15
  parallel L10 L14
  parallel L11 L15
  parallel L13 L16
  parallel L12 L17
  tangent L15 A1
  tangent L16 A1
  horizontal L18
  vertical L19
  horizontal L20
  vertical L21
  horizontal L22
  vertical L23
  horizontal L24
  vertical L25
  coincident P13 P27
  dimension "d187" radius A1 = 7
  dimension "d188" distance P26 P27 = 1
  dimension "d189" distance P21 P28 = 1
extrude "Extrude46" new body sketch "Sketch34" profile of L10 L11 L12 L13 L17 L16 L15 L14 A1 L18 L19 L20 L21 L22 L23 L24 L25 to an object
sketch "Sketch35" plane through (0, -17.45, 0) normal (0, -1, 0) x axis (1, 0, 0)
  line L1 (140.4667, 75.3543) -> (136.4646, 75.3543)
  line L2 (140.4667, 85.3543) -> (140.4667, 75.3543)
  line L3 (136.4646, 85.3543) -> (140.4667, 85.3543)
  line L4 (136.4646, 75.3543) -> (136.4646, 85.3543)
  circle C1 centre (140.3688, 80.3543) radius 1.5
  circle C2 centre (158.8374, 80.3543) radius 1.5
extrude "Extrude47" cut sketch "Sketch35" profile of L2 C1 C2 along normal blind 18 and against normal blind 14
sketch "Sketch36" plane through (0, -17.45, 0) normal (0, -1, 0) x axis (1, 0, 0)
  line L1 (158.7396, 75.3543) -> (158.7396, 78.8575)
  line L2 (162.7416, 75.3543) -> (158.7396, 75.3543)
  line L3 (162.7416, 85.3543) -> (162.7416, 75.3543)
  line L4 (158.7396, 85.3543) -> (162.7416, 85.3543)
  line L5 (158.7396, 81.8511) -> (158.7396, 85.3543)
  arc A1 centre (158.8374, 80.3543) radius 1.5 clockwise from (158.7396, 81.8511) to (158.7396, 78.8575)
  arc A2 centre (140.3688, 80.3543) radius 1.5 clockwise from (140.4667, 78.8575) to (140.4667, 81.8511)
  arc A3 centre (158.8374, 80.3543) radius 1.5 clockwise from (158.7396, 81.8511) to (158.7396, 78.8575)
  circle C1 centre (140.3688, 80.3543) radius 3.5
  circle C2 centre (158.8374, 80.3543) radius 3.5
  concentric A2 C1
  concentric A3 C2
  dimension "d196" diameter C1 = 7
  dimension "d197" diameter C2 = 7
extrude "Extrude48" cut sketch "Sketch36" profile of A1 L1 L5 A3 C1 C2 along normal blind 4
fillet "Fillet9" radius 1 bodies "Body1 (1)"
fillet "Fillet10" radius 1 bodies "Body1 (1)"
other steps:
derived_base_feature "Derived Base Feature1" bodies "Hotplate Cam Template"
derived_base_feature "Derived Base Feature2" bodies "Body1"
derived_base_feature "Derived Base Feature3" bodies "Body1 (1)"
derived_base_feature "Derived Base Feature4" bodies "Body1 (2)"
derived_base_feature "Derived Base Feature5" bodies "Body1 (3)", "Body2", "Body3"
derived_base_feature "Derived Base Feature6" bodies "Body1 (4)"
derived_base_feature "Derived Base Feature7" bodies "Body1 (5)"
derived_base_feature "Derived Base Feature8" bodies "Body1 (6)"
base_feature "Base Feature1"
base_feature "Base Feature2"
base_feature "Base Feature3"
named bodies: "Hotplate Cam Template", "Body1", "Body1 (1)", "Hotplate Cam Template (1)", "Body1 (2)", "Body1 (3)", "Body2", "Body3", "Body1 (4)", "Body1 (5)", "Body1 (6)"

design "M3x20-FHCS"
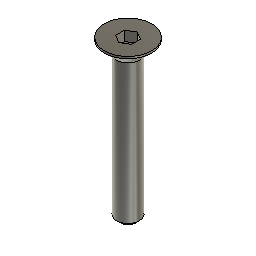
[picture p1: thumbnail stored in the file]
sketch "Sketch1" plane through (0, 0, 0) normal (0, 1, 0) x axis (1, 0, 0)
  line L1 (0, 20) -> (0, 0)
  line L2 (0.95, 20) -> (0, 20)
  line L3 (1.45, 19.5) -> (0.95, 20)
  line L4 (1.45, 1.8) -> (1.45, 19.5)
  line L5 (3, 0.25) -> (1.45, 1.8)
  line L6 (3, 0) -> (3, 0.25)
  line L7 (0, 0) -> (3, 0)
  point P1 (0, 0)
  point P2 (0, 0)
  point P9 (0, 0)
  point P3 (0, 20)
  point P4 (0.95, 20)
  point P8 (3, 0)
  point P7 (3, 0.25)
  coincident P1 P2
  vertical L1
  perpendicular L1 L2
  perpendicular L2 L4
  parallel L3 L5
  parallel L4 L6
  perpendicular L6 L7
  coincident P1 P9
  dimension "d1" distance P3 L4 = 1.45 (= "( 2.9 / 2 ) * 1 mm")
  dimension "d3" angle L2 L3 = 45
  dimension "d5" distance P4 L4 = 0.5
  dimension "d6" distance P2 P3 = 20
  dimension "d7" distance P8 P9 = 3 (= "( 6 / 2 ) * 1 mm")
  dimension "d9" distance P7 P8 = 0.25
revolve "Revolve1" sketch "Sketch1" AlongAngle 360
sketch "Sketch2" plane through (0, 0, 0) normal (0, 0, 1) x axis (-1, 0, 0)
  line L1 (0, -1.1547) -> (-1, -0.5774)
  line L2 (1, -0.5774) -> (0, -1.1547)
  line L3 (1, 0.5774) -> (1, -0.5774)
  line L4 (0, 1.1547) -> (1, 0.5774)
  line L5 (-1, 0.5774) -> (0, 1.1547)
  line L6 (-1, -0.5774) -> (-1, 0.5774)
  circle C1 centre (0, 0) radius 3
  point P1 (0, 0)
  point P9 (0, 0)
  coincident P1 P9
  vertical L6
  dimension "d12" distance L3 L6 = 2
extrude "Extrude1" cut sketch "Sketch2" profile of L1 L2 L3 L4 L5 L6 against normal blind 1.26

design "Makita RT0700 v10"
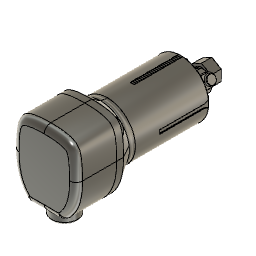
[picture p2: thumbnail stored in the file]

design "TE-10p-2p5-socket_1674231"
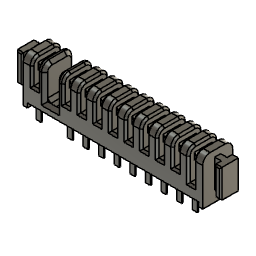
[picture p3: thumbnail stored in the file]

design "6806 Bearing"
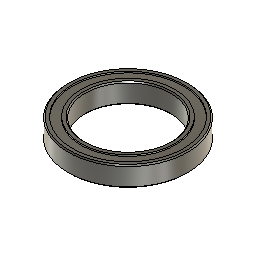
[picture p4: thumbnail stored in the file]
sketch "Sketch1" plane through (0, 0, 0) normal (0, 1, 0) x axis (1, 0, 0)
  line L1 (16.5, -3.5) -> (15, -3.5)
  line L2 (15, 3.5) -> (16.5, 3.5)
  line L3 (15, -3.5) -> (15, 3.5)
  line L4 (21, -3.5) -> (19.5, -3.5)
  line L5 (21, 3.5) -> (21, -3.5)
  line L6 (19.5, 3.5) -> (21, 3.5)
  line L7 (19.5, -3) -> (16.5, -3)
  line L8 (19.5, 3) -> (16.5, 3)
  line L9 (16.5, -3) -> (16.5, -3.5)
  line L10 (16.5, 3.5) -> (16.5, 3)
  line L11 (19.5, 3) -> (19.5, 3.5)
  line L12 (19.5, -3.5) -> (19.5, -3)
  line L13 (0, 0) -> (21, 0)
  point P11 (19.5, -3)
  point P12 (16.5, 3)
  point P14 (21, 0)
  point P1 (0, 0)
  point P15 (0, 0)
  point P16 (15, 0)
  point P6 (19.5, -3.5)
  point P2 (15, -3.5)
  point P3 (16.5, -3.5)
  point P10 (16.5, -3)
  point P7 (21, -3.5)
  point P8 (21, 3.5)
  horizontal L1
  vertical L9
  horizontal L2
  vertical L3
  horizontal L4
  vertical L5
  horizontal L6
  vertical L11
  coincident P11 L11
  perpendicular L7 L11
  coincident P12 L9
  perpendicular L8 L9
  collinear L9 L10
  collinear L11 L12
  midpoint L5 P14
  coincident P1 P15
  horizontal L13
  midpoint L3 P16
  coincident L13 P16
  equal L1 L4
  equal L9 L10
  coincident L1 P6
  dimension "d1" distance P1 L3 = 15 (= "( 30 / 2 ) * 1 mm")
  dimension "d2" distance P1 L5 = 21 (= "( 42 / 2 ) * 1 mm")
  dimension "d3" distance P2 P3 = 1.5
  dimension "d4" distance P3 P10 = 0.5
  dimension "d5" distance P7 P8 = 7
revolve "Revolve1" sketch "Sketch1" AlongAngle 360
chamfer "Chamfer1" distance 0.4

design "6x16-Dowel-Pull-Out"
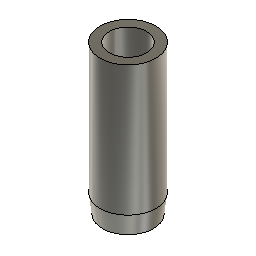
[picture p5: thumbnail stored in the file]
sketch "Sketch1" plane through (0, 0, 0) normal (0, 1, 0) x axis (1, 0, 0)
  line L1 (0, 16) -> (0, 0)
  line L2 (2.75, 16) -> (0, 16)
  line L3 (3, 14) -> (2.75, 16)
  line L4 (3, 0) -> (3, 14)
  line L5 (0, 0) -> (3, 0)
  line L6 (2, 5.5) -> (2, 0)
  line L7 (0, 5.5) -> (2, 5.5)
  point P1 (0, 0)
  point P2 (0, 0)
  point P7 (0, 0)
  point P8 (2, 0)
  point P10 (0, 5.5)
  point P6 (3, 0)
  point P3 (0, 16)
  point P4 (2.75, 16)
  point P5 (3, 14)
  point P9 (2, 5.5)
  coincident P1 P2
  vertical L1
  perpendicular L1 L2
  perpendicular L2 L4
  coincident P1 P7
  horizontal L5
  coincident L5 P8
  perpendicular L5 L6
  coincident L1 P10
  perpendicular L1 L7
  dimension "d1" distance P6 P7 = 3
  dimension "d2" distance P2 P3 = 16
  dimension "d3" distance P4 L4 = 0.25
  dimension "d4" distance P4 P5 = 2
  dimension "d5" distance P8 P9 = 5.5
  dimension "d6" distance P9 P10 = 2
revolve "Revolve1" sketch "Sketch1" AlongAngle 360

design "Hotplate Tool Template" references "PCB Blade Drop", "M4x10-BHCS", "M4x14-BHCS", "6x16-Dowel-Pull-Out"
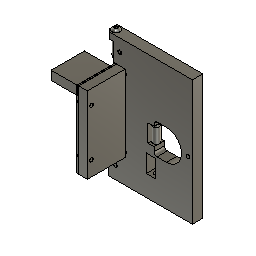
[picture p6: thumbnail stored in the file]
parameter "t_sheet_MAIN" = 7.9375 (= "5 / 16 * 1")
parameter "extrusion_w" = 20
parameter "extrusion_h" = 60
parameter "r_cutoutTool" = 2.05 (= "4.1 mm / 2")
parameter "od_bearings" = 13
parameter "id_bearings" = 4
parameter "t_bearings" = 5
parameter "preload" = 0.15
parameter "hw_m3_thru" = 3.5
parameter "hw_m3_thread" = 2.5
parameter "hw_m3_head" = 5.5
parameter "hw_m3_headheight" = 3
parameter "hw_m3_flathead" = 6
parameter "hw_m3_buttonhead" = 5.7
parameter "hw_m3_washer" = 7
parameter "hw_m3hex_d" = 5.5
parameter "hw_m3hex_t" = 4
parameter "hw_m3i_d" = 5.4
parameter "hw_m3i_l" = 3.8
parameter "hw_m3ichamfer" = 0.95 (= "( hw_m3i_d - hw_m3_thru ) / 2")
parameter "hw_m4_thru" = 4.25
parameter "hw_m4_head" = 7
parameter "hw_m4_headheight" = 4
parameter "hw_m4hex_d" = 7
parameter "hw_m4hex_t" = 5.2
parameter "hw_m4i_d" = 6
parameter "hw_m4i_l" = 4.8
parameter "hw_m4ichamfer" = 0.875 (= "( hw_m4i_d - hw_m4_thru ) / 2")
parameter "hw_m5_thread" = 4.2
parameter "hw_m5_head" = 8.5
parameter "hw_m5_washer" = 10
parameter "hw_m5_thru" = 5.25
parameter "hw_m6_thru" = 6.5
parameter "hw_m6_head" = 10
parameter "hw_m6_flathead" = 12
parameter "hw_m6_buttonhead" = 10.5
parameter "hw_m6_washer" = 12
parameter "p_belt" = 1.4
parameter "w_belt" = 10
parameter "t_belt" = 1.4
parameter "belt_pdo_toothside" = 1.15
parameter "belt_pdo_backside" = 0.25
parameter "t_m4_washer" = 0.85
parameter "flex_t" = 2.54
parameter "flex_l" = 5
parameter "t_motor_plates" = 6 comment "5/16 Phenolic"
parameter "swap_center_distance" = 40
parameter "pd_swap_drive" = 57.2958 (= "( nt_swap_drive * 2 / PI ) * 1 mm")
parameter "pd_swap_pinion" = 10.1859 (= "( nt_swap_pinion * 2 / PI ) * 1 mm")
parameter "od_mintool" = 2.1
parameter "t_sheet_THIN" = 5
parameter "c2c_spanners" = 14
parameter "c2c_height_pts" = 75
parameter "right_int_offset" = 30
parameter "d954" = 1.7
parameter "d1221" = 5
parameter "d1747" = 9
parameter "d1748" = 5.5 (= "t_sheet_THIN + 0.5 mm")
parameter "d1761" = 2
parameter "d1917" = 5
parameter "d2148" = 60
parameter "d2184" = 3
parameter "d2185" = 3 (= "d2184")
parameter "d2474" = 5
